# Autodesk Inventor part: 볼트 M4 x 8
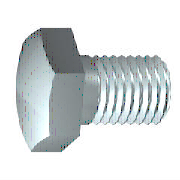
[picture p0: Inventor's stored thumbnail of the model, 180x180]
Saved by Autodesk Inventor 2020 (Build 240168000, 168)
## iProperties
Created: 2012-02
Part Number: 볼트 M4 x 8
Material: 스테인리스강
Description: 6각 머리 나사
Document SubType Name: Modeling
Standard: ISO 4017
Designer: mduedu
Standard Revision: Third edition 1999-08-15
Standards Organization: ISO
Language: ko-KR
Size Designation: M4 x 10
Categories: <MemberInstance><Categories><Category DisplayName="조임쇠" InternalName="e4da775c-781d-43d5-af7c-5136215cf5a6" Mnemonic="FSTN"><Category DisplayName="볼트" InternalN
Density: 8.08 g/cm^3
Appearance: 반광택
IsCustomPart: 0
Author: mduedu
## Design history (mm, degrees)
sketch "스케치1"
  geometry: L1 (0, 3.015)-(0, 2); L2 (1.75, 2)-(8, 2); L3 (8, 2)-(8, 0); L4 (8, 0)-(-0.4, 0); L5 (-2.08, 0)-(9.68, 0) reference; L6 (-0.4, 0)-(-0.4, 3.015); L7 (-0.4, 3.015)-(0, 3.015); L8 (1.75, 2)-(1.32, 2); L9 (1.32, 2)-(0, 2); L10 (0, -0.603)-(0, 3.618) reference
  constraints: 16 end point, 2 collinear, 2 perpendicular, 1 parallel
  dimensions: "d0" = 8 distance between parallel lines of L3 L1 (= NLG); "d1" = 6.25 distance from line of L2.start L3 (= GEL); "d2" = 4 diameter of L2 L4 (= GD); "d9" = 0.4001 distance between parallel lines of L6 L1 (computed from SD); "d10" = 6.03 diameter of L7 L4 (= SD2); "d13" = 0.42952 distance of L2.start L8.end (computed from GAL); "d14" = 4 diameter of L9 L4 (= BDM)
revolve "본체" sketch "스케치1" stored, may be unused: angle "d12" = 90 deg
sketch "스케치2"
  geometry: L1 (0, 4.041)-(3.5, 2.021); L2 (3.5, 2.021)-(3.5, -2.021); L3 (3.5, -2.021)-(0, -4.041); L4 (0, -4.041)-(-3.5, -2.021); L5 (-3.5, -2.021)-(-3.5, 2.021); L6 (-3.5, 2.021)-(0, 4.041); 2 further points
  constraints: 12 end point, 1 coincident, 1 vertical, 11 other
  dimensions: "d11" = 7 distance between parallel lines of L5 L2 (= SW)
extrude "머리" join sketch "스케치2" distance "d3" = 2.4 (= KOH - SD); taper "d4" = 0 deg
sketch "스케치4"
  geometry: L1 (-2.8, 3.5)-(-2.8, 4.041); L2 (-2.8, 4.041)-(-2.487, 4.041); L3 (-2.487, 4.041)-(-2.8, 3.5); L4 (-3.28, 0)-(0.08, 0) reference; L5 (-0.4, 4.041)-(-2.8, 4.041) reference; L6 (-2.8, 2.021)-(-2.8, 4.041) reference
  constraints: 6 end point, 2 collinear, 1 perpendicular, 1 vertical
  dimensions: "d5" = 30 deg angle of L3 L1 (= ANG1); "d19" = 7 diameter of L1.start L4 (= SW0)
revolve "모따기1" sketch "스케치4" stored, may be unused: angle "d21" = 90 deg
workplane "Work Plane1"
body "Solid1"
feature "스레드" dims "d15" = 6.25 (= GEL), "d16" = 0
chamfer "모따기2" distance "d6" = 0.42941 (= -0.5 x SPD + 0.5 x GD); stored, may be unused: second distance "d7" = 0.42952 (computed from GUL), angle "d55" = 45 deg
other parameters: "NLG" = 8 [user parameter; used in 1 equation term], "GD" = 4 (= NND) [user parameter; used in 2 equation terms], "BDM" = 4 (= NND) [user parameter; used in 1 equation term], "KOH" = 2.8 [user parameter; used in 1 equation term], "GEL" = 6.25 [user parameter; used in 2 equation terms], "SW" = 7 [user parameter; used in 2 equation terms], "SW0" = 7 (= SW) [user parameter; used in 1 equation term], "SPD" = 3.14117 (= NND - 1.2269 x PTC) [user parameter; used in 1 equation term], "SD2" = 6.03 [user parameter; used in 2 equation terms], "SD" = 0.4 [user parameter; used in 2 equation terms], "ANG1" = 30 deg [user parameter; used in 1 equation term], "GAL" = 0.42941 (= 0.61345 x PTC) [user parameter; used in 1 equation term], "GUL" = 0.42941 (= 0.61345 x PTC) [user parameter; used in 1 equation term], "d8" = 0, "RR" = 0.2 [user parameter], "d57" = 0, "d58" = 0, "TPU" = 14.28571 (computed from PTC) [user parameter], "GD1" = 3.14117 (= THREADDIA - 1.2269 x PTC) [user parameter], "THREADDIA" = 4 [user parameter; used in 1 equation term], "SDH" = 6.03 (= SD2) [user parameter], "SDHG" = 2.1 [user parameter], "TOA" = 30 deg [user parameter], "PTC" = 0.7 [user parameter; used in 5 equation terms], "NND" = 4 [user parameter; used in 3 equation terms], "E0" = 8.085 [user parameter]
